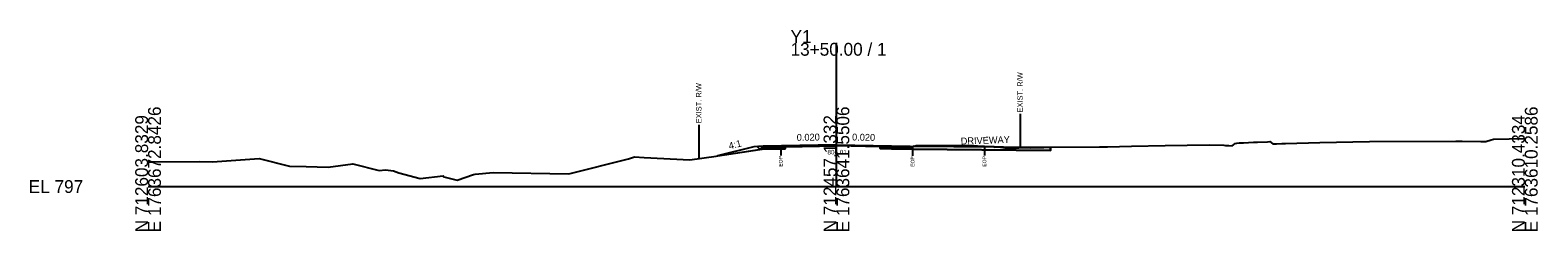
# Model space of a CAD drawing. Extents: x -26 to 1303, y -10 to 9524.
# Drawn here: x -25.7 to 302.8, y 3490.3 to 3534.2 of the extents above; entities that cross this region are included whole.
import ezdxf

# ---------------------------------------------------------------- set-up
doc = ezdxf.new("R2010")
doc.units = 0
for name, color, linetype in [('Default', 7, 'Continuous'), ('Exist CMT Pavement', 7, 'Continuous'), ('Exist Cross Section Cell', 7, 'Continuous'), ('Exist XS Center Line Elevation Label', 7, 'Continuous'), ('Exist XS Ground Line', 7, 'Continuous'), ('Old_Level_10', 7, 'Continuous'), ('Prop CMT Pvmt Course 1', 7, 'Continuous'), ('Prop CMT Pvmt Course 3', 7, 'Continuous'), ('Prop CMT Pvmt Surface', 7, 'Continuous'), ('Prop CMT Pvmt Surface Shoulder', 7, 'Continuous'), ('Prop CMT Shld Paved Course 1', 7, 'Continuous'), ('Prop CMT Shld Paved Course 3', 7, 'Continuous'), ('Prop CMT Slope Grass', 7, 'Continuous'), ('Prop CMT Subgrade Earthwork', 7, 'Continuous'), ('Prop XS Earthwork Shape', 7, 'Continuous'), ('Prop XS SE Text', 7, 'Continuous'), ('Prop XS Side Slope Text', 7, 'Continuous')]:
    doc.layers.add(name, color=color, linetype=linetype)

msp = doc.modelspace()

# ---------------------------------------------------------------- linework, layer by layer
at = {"layer": 'Exist CMT Pavement'}
msp.add_lwpolyline([(138.86, 3508.82), (139.69, 3508.83), (140.68, 3508.85), (141.01, 3508.85), (143.23, 3508.89), (144.26, 3508.9), (145.79, 3508.92), (147.51, 3508.97), (148.35, 3508.99), (149.65, 3509.02), (150, 3509.01), (150.9, 3509), (151.44, 3509), (153.46, 3508.99), (155.21, 3508.97), (156.02, 3508.96), (157.26, 3508.93), (158.57, 3508.89), (159.53, 3508.89), (159.53, 3508.89)], dxfattribs=at)
at = {"layer": 'Exist Cross Section Cell'}
for p, q in [((150, 3500), (150, 3531.38)), ((0, 3500), (150, 3500)), ((150, 3500), (300, 3500))]:
    msp.add_line(p, q, dxfattribs=at)
at = {"layer": 'Exist XS Ground Line'}
msp.add_lwpolyline([(0, 3505.39), (1.1, 3505.39), (11.31, 3505.47), (14.05, 3505.39), (24.2, 3506.1), (30.82, 3504.43), (34.43, 3504.37), (39.25, 3504.21), (44.65, 3504.97), (50.37, 3503.47), (51.76, 3503.64), (53.51, 3503.43), (54.62, 3503.03), (59.26, 3501.74), (64.31, 3502.32), (64.45, 3502.14), (67.38, 3501.38), (70.94, 3502.64), (71.25, 3502.73), (75.17, 3503.08), (91.7, 3502.77), (104.66, 3506.09), (106.01, 3506.5), (108.08, 3506.38), (118.05, 3505.83), (123.82, 3506.64), (124.12, 3506.69), (137.15, 3508.69), (137.49, 3508.75), (137.85, 3508.8), (138.86, 3508.82), (139.69, 3508.83), (140.68, 3508.85), (141.01, 3508.85), (143.23, 3508.89), (144.26, 3508.9), (145.79, 3508.92), (147.51, 3508.97), (148.35, 3508.99), (149.65, 3509.02), (150, 3509.01), (150.9, 3509), (151.44, 3509), (153.46, 3508.99), (155.21, 3508.97), (156.02, 3508.96), (157.26, 3508.93), (158.57, 3508.89), (159.53, 3508.89), (160.19, 3508.87), (161.13, 3508.84), (163.73, 3508.78), (166.13, 3508.75), (166.6, 3508.76), (166.9, 3508.84), (167.37, 3509), (174.16, 3509), (176.24, 3508.97), (179.95, 3509), (180.77, 3508.91), (182.24, 3508.8), (183.51, 3508.78), (184.33, 3508.78), (184.35, 3508.62), (185.3, 3508.66), (186.69, 3508.49), (188.19, 3508.46), (189.72, 3508.48), (191.06, 3508.5), (192.26, 3508.48), (195.22, 3508.53), (196.78, 3508.57), (207.32, 3508.66), (208.26, 3508.65), (209.03, 3508.65), (214.3, 3508.82), (221.64, 3509), (231.22, 3509.14), (234.45, 3509.02), (234.78, 3509), (235.48, 3508.95), (236.22, 3508.91), (236.52, 3509.14), (236.86, 3509.4), (237.25, 3509.47), (237.84, 3509.58), (238.69, 3509.58), (240.85, 3509.72), (241.76, 3509.72), (243.94, 3509.8), (244.47, 3509.81), (245.12, 3509.31), (245.89, 3509.34), (247.05, 3509.39), (247.86, 3509.38), (255.36, 3509.63), (266.15, 3509.82), (284.98, 3509.88), (286.36, 3509.89), (290.43, 3509.84), (291.48, 3509.83), (292.69, 3510.19), (293.18, 3510.34), (300, 3510.46)], dxfattribs=at)
at = {"layer": 'Old_Level_10'}
for p, q in [((190, 3515.88), (190, 3508.48)), ((120, 3513.5), (120, 3506.1)), ((137.85, 3508.8), (137.85, 3506.75)), ((166.6, 3508.76), (166.6, 3506.71)), ((182.24, 3508.8), (182.24, 3506.75))]:
    msp.add_line(p, q, dxfattribs=at)
at = {"layer": 'Prop CMT Pvmt Course 1'}
for points in [[(150, 3509.14), (138, 3508.9)], [(138, 3508.9), (138, 3508.65)], [(138.86, 3508.67), (150, 3508.89)], [(150, 3508.89), (150, 3509.14)], [(150, 3509.14), (162, 3508.9)], [(150, 3508.89), (150, 3508.89), (150, 3508.89)], [(159.53, 3508.7), (150, 3508.89)], [(162, 3508.9), (162, 3508.65)], [(138, 3508.65), (138.86, 3508.67)], [(138.86, 3508.67), (138.86, 3508.67)], [(162, 3508.65), (159.53, 3508.7)], [(159.53, 3508.7), (159.53, 3508.7)]]:
    msp.add_lwpolyline(points, dxfattribs=at)
at = {"layer": 'Prop CMT Pvmt Course 3'}
for points in [[(138.86, 3508.67), (138, 3508.65)], [(138, 3508.65), (138, 3508.23)], [(138, 3508.23), (138.86, 3508.25)], [(138.86, 3508.25), (138.86, 3508.67)], [(159.53, 3508.7), (162, 3508.65)], [(159.53, 3508.37), (159.53, 3508.7)], [(162, 3508.23), (159.53, 3508.28)], [(162, 3508.65), (162, 3508.23)]]:
    msp.add_lwpolyline(points, dxfattribs=at)
at = {"layer": 'Prop CMT Pvmt Surface'}
for points in [[(150, 3509.14), (138, 3508.9)], [(150, 3509.14), (162, 3508.9)]]:
    msp.add_lwpolyline(points, dxfattribs=at)
at = {"layer": 'Prop CMT Pvmt Surface Shoulder'}
msp.add_line((166, 3508.82), (196.63, 3508.57), dxfattribs=at)
for points in [[(138, 3508.9), (134, 3508.82)], [(162, 3508.9), (166, 3508.82)]]:
    msp.add_lwpolyline(points, dxfattribs=at)
at = {"layer": 'Prop CMT Shld Paved Course 1'}
for points in [[(138, 3508.9), (134, 3508.82), (133.74, 3508.56)], [(138, 3508.65), (138, 3508.9)], [(162, 3508.9), (166, 3508.82), (166.26, 3508.56)], [(162, 3508.65), (162, 3508.9)], [(133.74, 3508.56), (138, 3508.65)], [(166.26, 3508.56), (162, 3508.65)]]:
    msp.add_lwpolyline(points, dxfattribs=at)
at = {"layer": 'Prop CMT Shld Paved Course 3'}
for points in [[(133.74, 3508.56), (133.32, 3508.14)], [(133.32, 3508.14), (138, 3508.23)], [(138, 3508.65), (133.74, 3508.56)], [(138, 3508.32), (138, 3508.65)], [(162, 3508.65), (166.26, 3508.56)], [(162, 3508.32), (162, 3508.65)], [(166.68, 3508.14), (162, 3508.23)], [(166.26, 3508.56), (166.68, 3508.14)]]:
    msp.add_lwpolyline(points, dxfattribs=at)
at = {"layer": 'Prop CMT Slope Grass'}
msp.add_lwpolyline([(134, 3508.82), (132, 3508.66), (124.09, 3506.68)], dxfattribs=at)
at = {"layer": 'Prop CMT Subgrade Earthwork'}
for p, q in [((138.86, 3508.25), (138.86, 3508.82)), ((159.53, 3508.28), (159.53, 3508.89)), ((138, 3508.23), (133.32, 3508.14)), ((138.86, 3508.25), (138, 3508.23)), ((159.53, 3508.28), (161.99, 3508.23)), ((161.99, 3508.23), (166.68, 3508.14)), ((166.68, 3508.14), (196.62, 3507.9)), ((196.62, 3507.9), (196.63, 3508.57))]:
    msp.add_line(p, q, dxfattribs=at)
msp.add_lwpolyline([(132.74, 3508.72), (133.32, 3508.14)], dxfattribs=at)
at = {"layer": 'Prop XS Earthwork Shape'}
for points in [[(138, 3508.23), (133.63, 3508.15), (137.15, 3508.69), (137.49, 3508.75), (137.85, 3508.8), (138.86, 3508.82), (138.86, 3508.25)], [(188.19, 3508.46), (189.72, 3508.48), (191.06, 3508.5), (192.26, 3508.48), (195.22, 3508.53), (196.63, 3508.57), (196.62, 3507.9), (166.68, 3508.14), (161.99, 3508.23), (159.53, 3508.28), (159.53, 3508.89), (160.19, 3508.87), (161.13, 3508.84), (163.73, 3508.78), (166.13, 3508.75), (166.6, 3508.76), (166.79, 3508.81), (184.34, 3508.67), (184.35, 3508.62), (185.25, 3508.66), (185.32, 3508.66), (186.69, 3508.49)], [(182.24, 3508.8), (183.51, 3508.78), (184.33, 3508.78), (184.34, 3508.67), (166.79, 3508.81), (166.9, 3508.84), (167.37, 3509), (174.16, 3509), (176.24, 3508.97), (179.95, 3509), (180.77, 3508.91)], [(132, 3508.66), (124.09, 3506.68), (124.12, 3506.69), (133.63, 3508.15), (133.32, 3508.14), (132.74, 3508.72)]]:
    msp.add_lwpolyline(points, close=True, dxfattribs=at)

# ---------------------------------------------------------------- texts
at = {"layer": 'Default'}
msp.add_text('-', height=0.0001, dxfattribs=at).set_placement((0, 3500))
at = {"layer": 'Exist Cross Section Cell'}
for s, p in [('Y1', (140, 3531.38)), ('13+50.00 / 1', (140, 3528.58)), ('EL 797', (-26, 3498.6))]:
    msp.add_text(s, height=2.8, dxfattribs=at).set_placement(p)
for s, p in [('N 712603.8329', (0, 3490)), ('E 1763672.8426', (2.8, 3490)), ('N 712457.1332', (150, 3490)), ('E 1763641.5506', (152.8, 3490)), ('N 712310.4334', (300, 3490)), ('E 1763610.2586', (302.8, 3490))]:
    msp.add_text(s, height=2.8, rotation=90, dxfattribs=at).set_placement(p)
at = {"layer": 'Exist XS Center Line Elevation Label'}
msp.add_text('806.01', height=1, dxfattribs=at).set_placement((148.04, 3507.01))
at = {"layer": 'Old_Level_10'}
for s, height, p in [('EXIST. R/W', 1.181, (120.59, 3513.81)), ('EXIST. R/W', 1.181, (190.59, 3516.18)), ('EOP', 0.787, (138.25, 3504.35)), ('EOP', 0.787, (166.99, 3504.31)), ('EOP', 0.787, (182.64, 3504.35))]:
    msp.add_text(s, height=height, rotation=90, dxfattribs=at).set_placement(p)
at = {"layer": 'Prop XS SE Text'}
for rotation, p in [(1.1458, (141.36, 3509.97)), (358.8542, (153.4, 3510.07))]:
    msp.add_text('0.020', height=1.5, rotation=rotation, dxfattribs=at).set_placement(p)
at = {"layer": 'Prop XS Side Slope Text'}
for s, rotation, p in [('4:1', 14.0362, (126.72, 3508.11)), ('DRIVEWAY', 1.9648, (177.11, 3509.17))]:
    msp.add_text(s, height=1.5, rotation=rotation, dxfattribs=at).set_placement(p)

doc.saveas('drawing.dxf')
